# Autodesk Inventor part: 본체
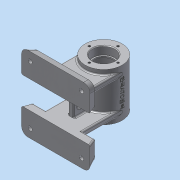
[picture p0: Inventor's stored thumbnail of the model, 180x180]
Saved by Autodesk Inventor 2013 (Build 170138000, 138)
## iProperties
Created: 2016-07
Part Number: 본체
Material: 알루미늄 6061
Document SubType Name: Modeling
Designer: Administrator
Density: 2.71 g/cm^3
Mass: 497.965 g
Surface Area: 541.299 cm^2
Volume: 183.751 cm^3
Author: Administrator
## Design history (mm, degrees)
sketch "스케치3"
  geometry: C1 r 27 at (0, 0); 1 further point
  constraints: 1 centre point, 1 coincident
  dimensions: "d4" = 54 diameter of C1
extrude "돌출1" new body sketch "스케치3" distance "d6" = 35; taper "d7" = 0 deg
sketch "스케치4"
  geometry: L1 (0, 0)-(-22, 0); L2 (-22, 0)-(-22, 21); L3 (-22, 21)-(-14, 21); L4 (-14, 21)-(-14, 23); L5 (-14, 23)-(-16, 23); L6 (-16, 23)-(-16, 35); L7 (-16, 35)-(0, 35); L8 (27, 35)-(-27, 35) reference; L9 (0, 0)-(0, 35); 1 further point
  constraints: 16 end point, 5 parallel, 2 perpendicular, 1 horizontal, 1 midpoint, 1 point on line
  dimensions: "d8" = 44 diameter of L2 L9; "d10" = 28 diameter of L4 L9; "d11" = 32 diameter of L6 L9; "d12" = 12 distance of L5.end L6.end; "d13" = 21 distance of L1.end L2.end
revolve "회전1" sketch "스케치4" stored, may be unused: angle "d14" = 90 deg
sketch "스케치5"
  geometry: C1 r 16 at (0, 0) reference; 1 further point
  constraints: 1 vertical alignment
  dimensions: "d15" = 21 distance of C1.centre point (0, 21)
hole "구멍1" sketch "스케치5" at (0, 21) diameter "d16" = 3.242; stored, may be unused: countersink angle "d20" = 90 deg, drill point angle "d22" = 118 deg; dims "d17" = 8, "d18" = 4, "d19" = 2, "d21" = 10
chamfer "모따기1" distance "d26" = 1; stored, may be unused: second distance "d27" = 2, angle "d28" = 45 deg
chamfer "모따기2" distance "d29" = 1; stored, may be unused: second distance "d30" = 2, angle "d31" = 45 deg
fillet "모깎기1" dims "d32" = 0.3
fillet "모깎기2" dims "d33" = 0.3
fillet "모깎기3" dims "d34" = 2
node "작업 평면1"
sketch "스케치7"
  geometry: L1 (-50, 55)-(50, 55); L2 (50, 55)-(50, -55); L3 (50, -55)-(-50, -55); L4 (-50, -55)-(-50, 55); 2 further points
  constraints: 8 end point, 2 parallel, 1 horizontal, 1 midpoint, 1 perpendicular, 1 vertical alignment
  dimensions: "d38" = 100 distance of L1.start L1.end; "d39" = 55 distance from line of L1 point (0, 0); "d51" = 110 distance of L1.end L2.end
extrude "돌출2" join sketch "스케치7" distance "d40" = 12; taper "d41" = -20 deg
sketch "스케치8"
  geometry: L1 (50, -55)-(-50, -55) reference; L2 (-50, -55)-(-50, 55) reference; 2 further points
  dimensions: "d42" = 12.5 distance from line of L1 point (-37.5, -42.5); "d43" = 12.5 distance from line of L2 point (-37.5, -42.5)
hole "구멍2" sketch "스케치8" at (-37.5, -42.5) diameter "d44" = 6; stored, may be unused: countersink angle "d48" = 90 deg, drill point angle "d50" = 0 deg; dims "d45" = 8, "d46" = 10, "d47" = 4, "d49" = 10
sketch "스케치9"
  geometry: L1 (50, 55)-(-50, 55) reference; L2 (50, -55)-(50, 55) reference; L3 (-50, 20)-(50, 20); L4 (50, 20)-(50, -20); L5 (50, -20)-(-50, -20); L6 (-50, -20)-(-50, 20); L7 (-50, 20)-(50, -20); L8 (50, 20)-(-50, -20); 4 further points
  constraints: 12 end point, 6 midpoint, 2 parallel, 1 horizontal, 1 perpendicular, 1 vertical alignment
  dimensions: "d52" = 35 distance from line of point (0, 55) L3
extrude "돌출3" cut sketch "스케치9" distance "d54" = 12; taper "d55" = 0 deg
sketch "스케치10"
  geometry: L1 (4.368, 12)-(95.632, 12) reference; L2 (23, 70)-(23, 12); L3 (77, 70)-(77, 12); L4 (23, 12)-(77, 12); C1 r 27 at (50, 70) reference; A1 r 27 centre (50, 70) between (23, 70) and (77, 70); 1 further point
  constraints: 6 end point, 2 perpendicular, 2 point on circle, 2 point on line, 2 tangent, 1 centre point, 1 coincident, 1 concentric, 1 parallel
extrude "돌출4" join sketch "스케치10" distance "d56" = 8; taper "d57" = 0 deg
node "작업 평면2"
sketch "스케치13"
  geometry: L1 (27, 35)-(-27, 35) reference; C1 r 5 at (0, 13); 1 further point
  constraints: 1 centre point, 1 vertical alignment
  dimensions: "d84" = 10 diameter of C1; "d86" = 22 distance from line of C1.centre L1
extrude "돌출7" join sketch "스케치13" stored distance "d87" = 8; taper "d88" = 0 deg
hole "구멍3" diameter "d91" = 5.188; stored, may be unused: countersink angle "d95" = 90 deg, drill point angle "d97" = 118 deg; dims "d92" = 6, "d93" = 4, "d94" = 2, "d96" = 8, "d148" = 10, "d149" = 10
sketch "스케치14"
  geometry: L1 (0, 0)-(-15.898, -25.441); L2 (0, 0)-(30, 0)
  constraints: 4 end point, 1 equal length, 1 horizontal
  dimensions: "d98" = 30 distance of L1.start L1.end; "d99" = 122 deg angle of L1 L2
node "작업 평면3"
sketch "스케치15"
  geometry: C1 r 6 at (0, 0); 1 further point
  constraints: 1 centre point, 1 coincident
  dimensions: "d100" = 12 diameter of C1
extrude "돌출8" join sketch "스케치15" stored distance "d102" = 10; taper "d103" = 0 deg
hole "구멍4" diameter "d106" = 5.188; stored, may be unused: countersink angle "d110" = 90 deg, drill point angle "d112" = 118 deg; dims "d107" = 6, "d108" = 4, "d109" = 2, "d111" = 8, "d144" = 10, "d145" = 10
node "작업 평면5"
sketch "스케치16"
  geometry: L1 (27, 35)-(-27, 35) reference; L2 (27, -35)-(27, 35) reference; 2 further points
  constraints: 1 other
  dimensions: "d115" = 35 distance from line of L1 point (0, 0); "d116" = 27 distance from line of point (0, 0) L2
feature "엠보싱1" sketch "스케치16" dims "d117" = 0.5, "d118" = 0
fillet "모깎기4" dims "d119" = 2
fillet "모깎기5" dims "d120" = 2
node "작업 평면6"
sketch "스케치17"
  geometry: L1 (-4, 20)-(4, 20); L2 (4, 20)-(4, -20); L3 (4, -20)-(-4, -20); L4 (-4, -20)-(-4, 20); L5 (-4, 20)-(4, -20); L6 (4, 20)-(-4, -20); L7 (50, 20)-(-50, 20) reference; 2 further points
  constraints: 12 end point, 4 midpoint, 2 parallel, 1 horizontal, 1 perpendicular
  dimensions: "d126" = 8 distance of L2.end L3.end
extrude "돌출9" join sketch "스케치17" stored distance "d128" = 10; taper "d129" = 0 deg
sketch "스케치18"
  geometry: L1 (0, 21.298)-(40, 21.298) reference; L2 (12, 13.5)-(28, 13.5); L3 (31.5, 10)-(31.5, 10); L4 (28, 6.5)-(12, 6.5); L5 (8.5, 10)-(8.5, 10); L6 (75, -22)-(40, -22) reference; A1 r 3.5 centre (12, 10) between (8.5, 10) and (12, 6.5); A2 r 3.5 centre (12, 10) between (12, 13.5) and (8.5, 10); A3 r 3.5 centre (28, 10) between (28, 6.5) and (31.5, 10); A4 r 3.5 centre (28, 10) between (31.5, 10) and (28, 13.5); 11 further points
  constraints: 8 end point, 8 point on circle, 8 tangent, 6 point on line, 5 midpoint, 4 centre point, 3 equal radius, 3 vertical alignment, 2 parallel, 1 horizontal, 1 perpendicular
  dimensions: "d130" = 23 distance of point (31.5, 6.5) point (8.5, 6.5); "d132" = 7 distance of point (31.5, 13.5) point (31.5, 6.5); "d133" = 3.5 radius of A1; "d134" = 32 distance from line of L6 A4.centre
extrude "돌출10" cut sketch "스케치18" stored distance "d135" = 10; taper "d136" = 0 deg
fillet "모깎기8" dims "d137" = 2
fillet "모깎기9" dims "d138" = 2
fillet "모깎기10" dims "d139" = 2
fillet "모깎기11" dims "d140" = 10
fillet "모깎기12" dims "d141" = 10
fillet "모깎기13" dims "d142" = 2
fillet "모깎기14" dims "d143" = 2
node "솔리드1"
pattern_circular "원형 패턴1" dims angle "d24" = 360 deg
mirror "대칭1"
mirror "대칭2"
mirror "대칭3"
mirror "대칭4"
other parameters: "d114" = 27, "d125" = -48
